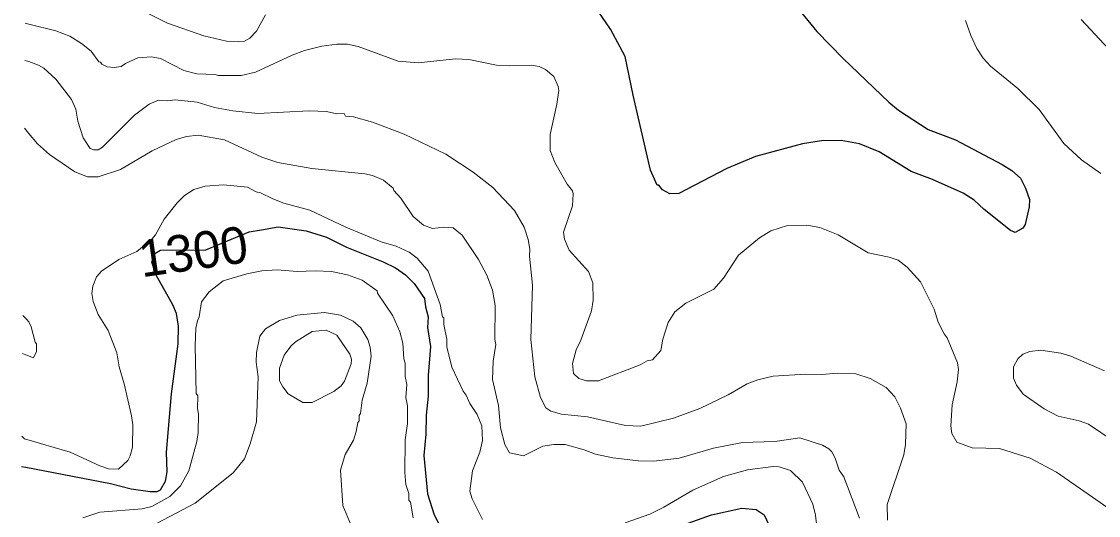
# Model space of a CAD drawing. Extents: x 598.3 to 623.2, y 6902.2 to 6930.1.
# Drawn here: x 598.422 to 600.767, y 6914.004 to 6915.078 of the extents above; entities that cross this region are included whole.
import ezdxf
from ezdxf.enums import TextEntityAlignment as Align

# ---------------------------------------------------------------- set-up
doc = ezdxf.new("R2010")
doc.units = 0
doc.header["$LTSCALE"] = 0.032
doc.layers.add('1', color=7, linetype='Continuous', lineweight=25)
doc.layers.add('2', color=7, linetype='Continuous', lineweight=13)
doc.layers.add('61', color=7, linetype='Continuous')

msp = doc.modelspace()

# ---------------------------------------------------------------- linework, layer by layer
at = {"layer": '1'}
for points in [[(600.0979, 6915.1255), (600.1538, 6915.0569), (600.2111, 6914.9975), (600.31, 6914.9029), (600.3311, 6914.8853), (600.3961, 6914.8433), (600.4554, 6914.8208), (600.5574, 6914.7674), (600.5779, 6914.7539), (600.5967, 6914.7375), (600.608, 6914.716), (600.6166, 6914.6909), (600.6162, 6914.6749), (600.6073, 6914.6366), (600.6019, 6914.6287), (600.5851, 6914.6195), (600.5751, 6914.6235), (600.5181, 6914.6691), (600.4964, 6914.6898), (600.4721, 6914.7047), (600.4052, 6914.735), (600.3587, 6914.7518), (600.2892, 6914.7949), (600.246, 6914.8121), (600.2061, 6914.8193), (600.1634, 6914.8185), (600.1219, 6914.8121), (600.0199, 6914.7846), (599.9574, 6914.7583), (599.8528, 6914.7044), (599.8332, 6914.7037), (599.8175, 6914.7123), (599.8091, 6914.722), (599.8059, 6914.7225), (599.7912, 6914.7552), (599.7532, 6914.9181), (599.7362, 6915.0025), (599.7041, 6915.0619), (599.6612, 6915.124)], [(598.4215, 6914.1104), (598.4306, 6914.1087), (598.6152, 6914.0731), (598.6605, 6914.062), (598.7015, 6914.056), (598.7168, 6914.056), (598.7242, 6914.0599), (598.7349, 6914.0781), (598.739, 6914.0986), (598.7374, 6914.1416), (598.7479, 6914.2685), (598.7624, 6914.377), (598.7634, 6914.4153), (598.759, 6914.443), (598.751, 6914.4618), (598.7146, 6914.5265), (598.7054, 6914.555), (598.7121, 6914.5738), (598.7244, 6914.581), (598.8226, 6914.582), (598.9173, 6914.6208), (598.9443, 6914.625), (598.9803, 6914.6314), (599.041, 6914.6228), (599.0853, 6914.609), (599.1295, 6914.5877), (599.2093, 6914.5556), (599.2357, 6914.5426), (599.2577, 6914.5273), (599.2762, 6914.5081), (599.2988, 6914.4758), (599.3009, 6914.458), (599.3072, 6914.4356), (599.3057, 6914.4126), (599.3121, 6914.3711), (599.3073, 6914.3084), (599.3072, 6914.2633), (599.3025, 6914.2222), (599.3017, 6914.1805), (599.2975, 6914.1346), (599.3056, 6914.0506), (599.3202, 6914.005), (599.3408, 6913.9636)], [(599.8142, 6913.9664), (599.9244, 6914.005), (599.9902, 6914.0195), (600.0212, 6914.0171), (600.0391, 6914.0054), (600.0487, 6913.9836)]]:
    msp.add_lwpolyline(points, dxfattribs=at)
at = {"layer": '2'}
for points in [[(598.9526, 6915.0927), (598.9332, 6915.0574), (598.9185, 6915.0418), (598.9071, 6915.0355), (598.8931, 6915.0339), (598.868, 6915.0355), (598.8185, 6915.0471), (598.7393, 6915.0744), (598.6752, 6915.1064)], [(598.4295, 6915.0747), (598.4371, 6915.0728), (598.4959, 6915.0582), (598.5264, 6915.0466), (598.5524, 6915.0302), (598.5728, 6915.0138), (598.5896, 6914.9907), (598.5934, 6914.9899), (598.5966, 6914.9853), (598.6082, 6914.98), (598.6235, 6914.9783), (598.6384, 6914.9804), (598.6478, 6914.9873), (598.6748, 6914.9992), (598.7037, 6915.0014), (598.7239, 6914.998), (598.7752, 6914.9721), (598.8036, 6914.9643), (598.8426, 6914.9633), (598.8505, 6914.961), (598.9, 6914.9608), (598.931, 6914.9678), (599.0105, 6915.0052), (599.0375, 6915.0154), (599.0757, 6915.0249), (599.1081, 6915.029), (599.1311, 6915.0289), (599.1549, 6915.0242), (599.2416, 6914.9921), (599.2855, 6914.9886), (599.3666, 6914.9974), (599.3958, 6914.9958), (599.4557, 6914.9837), (599.4844, 6914.9821), (599.5326, 6914.9836), (599.5488, 6914.9803), (599.5629, 6914.9739), (599.5808, 6914.9585), (599.5898, 6914.9373), (599.5913, 6914.9284), (599.5873, 6914.8986), (599.5728, 6914.8325), (599.5728, 6914.798), (599.583, 6914.7714), (599.6095, 6914.7247), (599.6214, 6914.7098), (599.623, 6914.7038), (599.6214, 6914.6771), (599.602, 6914.6199), (599.604, 6914.605), (599.6144, 6914.5808), (599.6561, 6914.5344), (599.6659, 6914.5099), (599.6666, 6914.4723), (599.6626, 6914.4487), (599.6395, 6914.3848), (599.6293, 6914.3642), (599.6215, 6914.3346), (599.6238, 6914.3128), (599.6353, 6914.3021), (599.6519, 6914.2964), (599.6783, 6914.2964), (599.7685, 6914.3318), (599.7839, 6914.3403), (599.7954, 6914.3426), (599.814, 6914.363), (599.8181, 6914.3873), (599.8299, 6914.4238), (599.8441, 6914.447), (599.868, 6914.4655), (599.9291, 6914.4958), (599.9499, 6914.5198), (599.9826, 6914.5701), (600.0285, 6914.6074), (600.0534, 6914.6233), (600.0892, 6914.6347), (600.1316, 6914.6355), (600.16, 6914.63), (600.1996, 6914.6144), (600.265, 6914.5751), (600.3108, 6914.566), (600.3304, 6914.5594), (600.3505, 6914.5443), (600.379, 6914.5117), (600.4093, 6914.4525), (600.4177, 6914.4246), (600.4306, 6914.3989), (600.4374, 6914.3901), (600.4599, 6914.3355), (600.4616, 6914.3217), (600.4593, 6914.2945), (600.4478, 6914.2444), (600.4455, 6914.1986), (600.4471, 6914.182), (600.4584, 6914.163), (600.4916, 6914.1513), (600.5509, 6914.1498), (600.6181, 6914.1283), (600.6756, 6914.0979), (600.7875, 6914.0208)], [(600.7717, 6914.7475), (600.7295, 6914.7772), (600.6916, 6914.8126), (600.6374, 6914.8871), (600.5912, 6914.9325), (600.5318, 6914.9814), (600.5154, 6914.9986), (600.5022, 6915.0198), (600.4891, 6915.0476), (600.4774, 6915.0806)], [(600.7293, 6915.0826), (600.8397, 6914.9648)], [(600.3063, 6914.028), (600.3426, 6914.1359), (600.3466, 6914.1585), (600.3482, 6914.2032), (600.3358, 6914.2371), (600.3232, 6914.2616), (600.3043, 6914.282), (600.2695, 6914.3018), (600.2382, 6914.3117), (600.1988, 6914.3133), (600.1643, 6914.3102), (600.1286, 6914.3109), (600.0583, 6914.3069), (600.0251, 6914.299), (600.0018, 6914.2899), (599.9603, 6914.2659), (599.8983, 6914.2363), (599.841, 6914.2153), (599.77, 6914.1984), (599.7366, 6914.1992), (599.654, 6914.2186), (599.5973, 6914.2243), (599.5742, 6914.231), (599.5632, 6914.2382), (599.552, 6914.2602), (599.5396, 6914.3055), (599.5307, 6914.3864), (599.5339, 6914.5047), (599.5276, 6914.5679), (599.5282, 6914.5829), (599.525, 6914.604), (599.5163, 6914.6309), (599.495, 6914.6671), (599.4478, 6914.7175), (599.405, 6914.7507), (599.3456, 6914.7896), (599.2544, 6914.8336), (599.1856, 6914.859), (599.1443, 6914.871), (599.1273, 6914.8727), (599.1244, 6914.8783), (599.1078, 6914.8776), (599.0858, 6914.8824), (599.0478, 6914.8841), (598.936, 6914.8783), (598.8813, 6914.8837), (598.842, 6914.8911), (598.8038, 6914.9026), (598.7562, 6914.9076), (598.7393, 6914.906), (598.7196, 6914.9075), (598.6997, 6914.8984), (598.6674, 6914.8747), (598.598, 6914.8051), (598.5887, 6914.7992), (598.5786, 6914.7991), (598.5707, 6914.8021), (598.5555, 6914.8253), (598.5443, 6914.8613), (598.5394, 6914.888), (598.53, 6914.9085), (598.4963, 6914.9527), (598.47, 6914.9765), (598.4587, 6914.9837), (598.4371, 6914.991), (598.4288, 6914.9938)], [(598.4276, 6914.8461), (598.4369, 6914.8351), (598.4562, 6914.8122), (598.4822, 6914.7889), (598.5373, 6914.751), (598.565, 6914.7406), (598.5887, 6914.7408), (598.6368, 6914.7561), (598.7059, 6914.7971), (598.7579, 6914.8215), (598.7806, 6914.8281), (598.806, 6914.8314), (598.8635, 6914.821), (598.9449, 6914.7835), (598.98, 6914.7716), (599.054, 6914.7585), (599.1694, 6914.7473), (599.1856, 6914.7433), (599.2096, 6914.733), (599.2309, 6914.7158), (599.232, 6914.7109), (599.2478, 6914.6944), (599.2742, 6914.6539), (599.2972, 6914.6352), (599.3166, 6914.6283), (599.3408, 6914.6307), (599.3615, 6914.6298), (599.3814, 6914.6139), (599.4164, 6914.5606), (599.435, 6914.5266), (599.4473, 6914.4942), (599.4529, 6914.4605), (599.4521, 6914.3865), (599.4545, 6914.3755), (599.4485, 6914.3397), (599.4474, 6914.2997), (599.4603, 6914.2427), (599.4644, 6914.1942), (599.4742, 6914.1583), (599.4838, 6914.1402), (599.5145, 6914.1337), (599.5566, 6914.1547), (599.5804, 6914.1579), (599.6051, 6914.1579), (599.6467, 6914.1468), (599.6713, 6914.137), (599.7093, 6914.1293), (599.7649, 6914.1227), (599.7987, 6914.1216), (599.8536, 6914.1286), (599.9284, 6914.1499), (599.9919, 6914.1628), (600.0623, 6914.1648), (600.1167, 6914.1725), (600.1656, 6914.157), (600.1798, 6914.149), (600.1863, 6914.1424), (600.1937, 6914.1286), (600.2023, 6914.1026), (600.2121, 6914.0878), (600.2464, 6913.998)], [(599.4192, 6914.1418), (599.4254, 6914.1668), (599.4238, 6914.1987), (599.414, 6914.2238), (599.3978, 6914.2473), (599.3898, 6914.2656), (599.3831, 6914.2742), (599.3588, 6914.3261), (599.3478, 6914.3703), (599.3477, 6914.387), (599.3413, 6914.4192), (599.3412, 6914.4337), (599.3381, 6914.436), (599.3328, 6914.4625), (599.3073, 6914.5349), (599.2829, 6914.5636), (599.2655, 6914.5767), (599.2374, 6914.5895), (599.2044, 6914.5987), (599.1278, 6914.6307), (599.0496, 6914.668), (598.9927, 6914.6835), (598.9684, 6914.6925), (598.942, 6914.7057), (598.9328, 6914.7078), (598.9133, 6914.7183), (598.8615, 6914.7229), (598.8216, 6914.7205), (598.7968, 6914.713), (598.7762, 6914.6998), (598.7602, 6914.6842), (598.7324, 6914.6483), (598.7134, 6914.6142), (598.7053, 6914.6051), (598.6723, 6914.5782), (598.6334, 6914.5605), (598.5953, 6914.5356), (598.5849, 6914.5231), (598.5769, 6914.5027), (598.5747, 6914.4865), (598.5772, 6914.4694), (598.5883, 6914.4408), (598.6103, 6914.4064), (598.629, 6914.3577), (598.6341, 6914.3272), (598.6451, 6914.2902), (598.6611, 6914.2209), (598.6637, 6914.2008), (598.6629, 6914.1521), (598.6584, 6914.1339), (598.6531, 6914.1231), (598.6327, 6914.1046), (598.6112, 6914.1054), (598.5917, 6914.1118), (598.5276, 6914.1413), (598.4278, 6914.1708), (598.4234, 6914.175), (598.4221, 6914.1763)], [(599.262, 6914.2426), (599.2587, 6914.2602), (599.2603, 6914.2889), (599.2571, 6914.3059), (599.257, 6914.3352), (599.2539, 6914.3447), (599.2522, 6914.3789), (599.245, 6914.403), (599.2302, 6914.4383), (599.1964, 6914.4877), (599.1962, 6914.4922), (599.163, 6914.5158), (599.1311, 6914.527), (599.0963, 6914.5344), (599.0608, 6914.536), (599.0214, 6914.5344), (598.9781, 6914.5384), (598.9449, 6914.536), (598.912, 6914.5295), (598.8609, 6914.5143), (598.8304, 6914.4906), (598.8134, 6914.4685), (598.8086, 6914.4357), (598.8045, 6914.4273), (598.8013, 6914.4111), (598.7997, 6914.3728), (598.8021, 6914.2692), (598.8053, 6914.2638), (598.8045, 6914.2368), (598.8071, 6914.2241), (598.8064, 6914.1845), (598.8036, 6914.1647), (598.7859, 6914.1006), (598.7678, 6914.0685), (598.7446, 6914.0452), (598.7056, 6914.0235), (598.6842, 6914.018), (598.592, 6914.0107), (598.5547, 6913.9985)], [(598.4235, 6914.3559), (598.4307, 6914.3531), (598.4473, 6914.3466), (598.4541, 6914.3605), (598.454, 6914.377), (598.4509, 6914.3805), (598.4428, 6914.4143), (598.4377, 6914.4253), (598.4323, 6914.4308), (598.4242, 6914.439)], [(598.7156, 6913.9867), (598.7997, 6914.0303), (598.8824, 6914.0965), (598.9067, 6914.1272), (598.9195, 6914.1593), (598.9332, 6914.2073), (598.9366, 6914.3055), (598.9325, 6914.3376), (598.9333, 6914.3585), (598.9406, 6914.394), (598.953, 6914.41), (598.983, 6914.4281), (599.0207, 6914.4396), (599.0812, 6914.4454), (599.116, 6914.4397), (599.1435, 6914.4268), (599.1601, 6914.4119), (599.1758, 6914.3863), (599.1808, 6914.3698), (599.1826, 6914.3501), (599.1745, 6914.2915), (599.1632, 6914.2546), (599.1599, 6914.2254), (599.1567, 6914.2216), (599.1566, 6914.21), (599.1535, 6914.2059), (599.1503, 6914.1866), (599.1441, 6914.1678), (599.1263, 6914.1368), (599.1163, 6914.1024), (599.1212, 6914.0256), (599.1427, 6913.9731)], [(600.8007, 6914.1646), (600.7452, 6914.2023), (600.725, 6914.2099), (600.6793, 6914.2198), (600.6483, 6914.2361), (600.6028, 6914.2678), (600.5884, 6914.2875), (600.5814, 6914.3023), (600.5815, 6914.3274), (600.5913, 6914.3443), (600.6022, 6914.3545), (600.6173, 6914.3604), (600.6416, 6914.3635), (600.6848, 6914.3571), (600.7066, 6914.3507), (600.7797, 6914.3186)], [(599.274, 6913.9988), (599.2684, 6914.0325), (599.2652, 6914.0368), (599.2651, 6914.0519), (599.2587, 6914.0714), (599.2563, 6914.097), (599.257, 6914.1681), (599.2619, 6914.2036), (599.262, 6914.2426)], [(599.4253, 6913.9947), (599.403, 6914.0402), (599.398, 6914.0568), (599.4037, 6914.1008), (599.4192, 6914.1418)], [(600.1531, 6913.9793), (600.1508, 6914.0048), (600.1444, 6914.0287), (600.1224, 6914.0762), (600.0962, 6914.1013), (600.0714, 6914.1093), (600.0585, 6914.1101), (600.0021, 6914.103), (599.95, 6914.0883), (599.8834, 6914.0591), (599.8201, 6914.0218), (599.7894, 6914.007), (599.7363, 6913.9879)], [(600.307, 6913.9937), (600.3063, 6914.028)]]:
    msp.add_lwpolyline(points, dxfattribs=at)
msp.add_lwpolyline([(599.0025, 6914.2685), (598.9905, 6914.2834), (598.9833, 6914.297), (598.9832, 6914.3246), (598.9937, 6914.3523), (599.0079, 6914.3718), (599.0182, 6914.3812), (599.0547, 6914.404), (599.0852, 6914.4072), (599.108, 6914.3959), (599.1363, 6914.3548), (599.1404, 6914.3436), (599.1397, 6914.3337), (599.125, 6914.2962), (599.1179, 6914.286), (599.1017, 6914.2735), (599.0541, 6914.2498), (599.0339, 6914.2494)], close=True, dxfattribs=at)

# ---------------------------------------------------------------- texts
at = {"layer": '61'}
msp.add_text('1300', height=0.08, rotation=8.13, dxfattribs=at).set_placement((598.801, 6914.5386), align=Align.CENTER)

doc.saveas('drawing.dxf')
